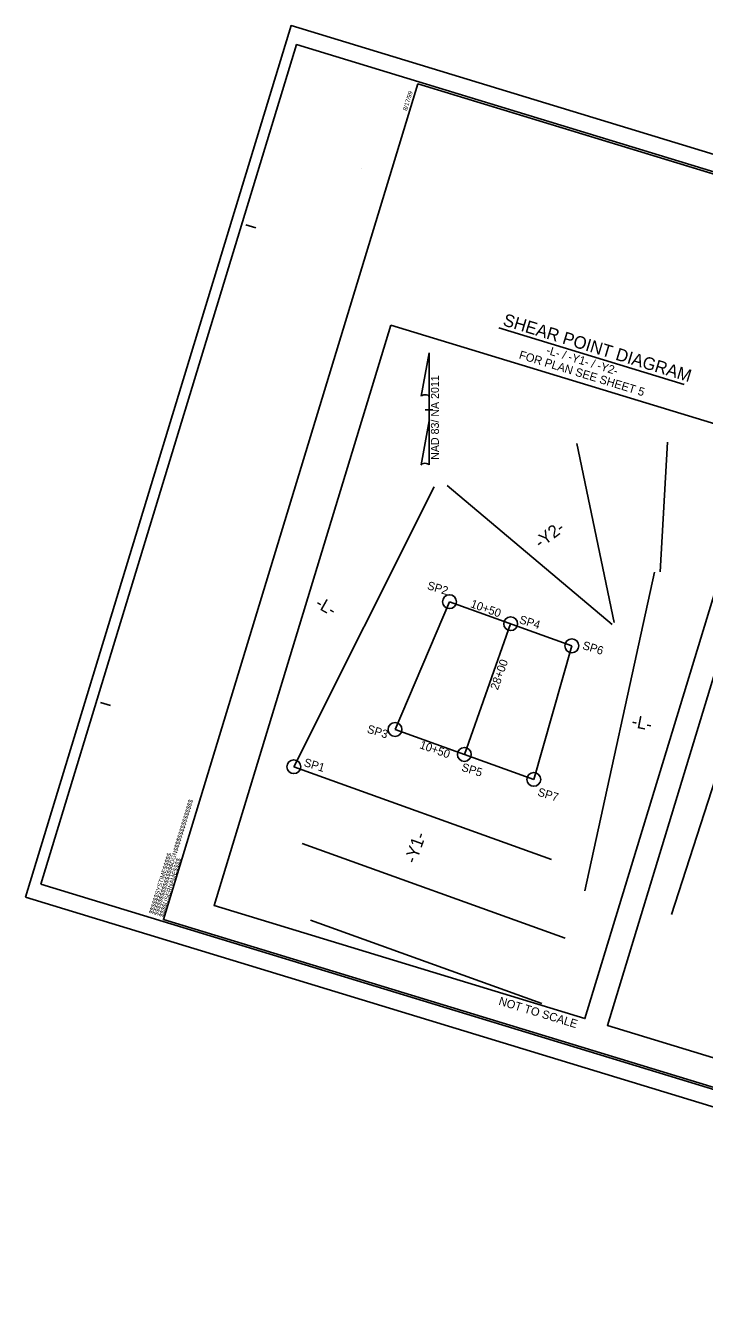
# Model space of a CAD drawing. Extents: x 1619199 to 1620423, y 897643 to 898566.
# Drawn here: x 1619199 to 1619689, y 897643 to 898566 of the extents above; entities that cross this region are included whole.
import ezdxf

# ---------------------------------------------------------------- set-up
doc = ezdxf.new("R2010")
doc.units = 0
for name, color, linetype in [('Default', 7, 'Continuous'), ('Prop North Arrow NAD83 for Plan Sheets CELL', 7, 'Continuous'), ('Sheet Plan CELL', 7, 'Continuous'), ('Sheet Plot Border Inside CELL', 7, 'Continuous'), ('Sheet Plot Border Outside CELL', 7, 'Continuous')]:
    doc.layers.add(name, color=color, linetype=linetype)

msp = doc.modelspace()

# ---------------------------------------------------------------- linework, layer by layer
at = {"layer": 'Default'}
for p, q in [((1619540.4, 898347.62), (1619674.25, 898306.83)), ((1619596.78, 898264.34), (1619623.54, 898135.11)), ((1619662.14, 898265.23), (1619656.92, 898171.77)), ((1619493.85, 898232.98), (1619392.46, 898031.21)), ((1619503.07, 898234.12), (1619622.08, 898133.89)), ((1619652.82, 898171.6), (1619602.45, 897941.66)), ((1619504.77, 898150.21), (1619465.48, 898058.08)), ((1619504.77, 898150.21), (1619593.11, 898118.44)), ((1619548.93, 898134.33), (1619515.52, 898040.08)), ((1619593.11, 898118.44), (1619565.59, 898022.07)), ((1619714.16, 898076.98), (1619664.97, 897924.73)), ((1619565.59, 898022.07), (1619465.48, 898058.08)), ((1619578.49, 897964.29), (1619392.46, 898031.21)), ((1619588.37, 897907.6), (1619398.52, 897975.89)), ((1619571.44, 897860.55), (1619404.59, 897920.57))]:
    msp.add_line(p, q, dxfattribs=at)
for points in [[(1619462.5, 898349.68), (1619730.07, 898268.15), (1619602.5, 897849.59), (1619334.95, 897931.12)], [(1620036.23, 898176.17), (1619908.29, 897756.39), (1619618.7, 897844.65), (1619746.28, 898263.24)], [(1620035.83, 898174.97), (1619908.21, 897756.39), (1619618.7, 897844.65), (1619746.31, 898263.23)]]:
    msp.add_lwpolyline(points, close=True, dxfattribs=at)
for centre in [(1619504.77, 898150.21), (1619548.93, 898134.33), (1619593.11, 898118.44), (1619465.48, 898058.08), (1619515.52, 898040.08), (1619392.46, 898031.21), (1619565.59, 898022.07)]:
    msp.add_circle(centre, 5, dxfattribs=at)
at = {"layer": 'Prop North Arrow NAD83 for Plan Sheets CELL'}
for p, q in [((1619484.47, 898298.42), (1619490.01, 898329.7)), ((1619490.04, 898329.7), (1619490.01, 898329.7)), ((1619490.04, 898329.7), (1619490.01, 898329.7)), ((1619490.04, 898329.7), (1619490.04, 898297.44)), ((1619490.04, 898280.7), (1619490.04, 898298.38)), ((1619490.04, 898297.44), (1619490.04, 898298.35)), ((1619487.34, 898288.53), (1619487.31, 898288.53)), ((1619489.74, 898288.53), (1619487.34, 898288.53)), ((1619487.38, 898288.53), (1619492.78, 898288.53)), ((1619490.04, 898280.7), (1619484.41, 898248.81)), ((1619490.08, 898248.94), (1619490.04, 898280.7))]:
    msp.add_line(p, q, dxfattribs=at)
for centre, start_param, end_param in [((1619487.27, 898298.08), 0.216388, 2.908219), ((1619487.27, 898248.69), 0.201328, 3.141593)]:
    msp.add_ellipse(centre, major_axis=(2.86, -0.02), ratio=0.461098, start_param=start_param, end_param=end_param, dxfattribs=at)
at = {"layer": 'Sheet Plan CELL'}
for p, q in [((1619441.3, 898462.92), (1619441.3, 898462.92)), ((1619357.91, 898421.91), (1619365.09, 898419.74)), ((1619252.97, 898077.56), (1619260.14, 898075.36))]:
    msp.add_line(p, q, dxfattribs=at)
for points in [[(1620342.99, 898261.25), (1619482.06, 898523.65), (1619298.39, 897921.02), (1620159.3, 897658.63)], [(1619298.39, 897921.02), (1619482.05, 898523.64), (1620228.16, 898296.26), (1620201.92, 898210.13), (1620316.72, 898175.13), (1620159.3, 897658.63)]]:
    msp.add_lwpolyline(points, close=True, dxfattribs=at)
at = {"layer": 'Sheet Plot Border Inside CELL'}
msp.add_lwpolyline([(1619209.86, 897946.43), (1620166.03, 897655.01), (1620350.58, 898260.5), (1619394.41, 898551.93)], close=True, dxfattribs=at)
at = {"layer": 'Sheet Plot Border Outside CELL'}
msp.add_lwpolyline([(1619198.9, 897937.22), (1620165.12, 897642.73), (1620356.66, 898271.19), (1619390.44, 898565.68)], close=True, dxfattribs=at)

# ---------------------------------------------------------------- texts
at = {"layer": 'Default'}
for s, height, rotation, p in [('SHEAR POINT DIAGRAM', 9, 343.04954, (1619542.77, 898349.63)), ('-L- / -Y1- / -Y2-', 6, 343.04954, (1619574.16, 898329.14)), ('FOR PLAN SEE SHEET 5', 6, 343.04954, (1619554.5, 898325.72)), ('-Y2-', 9, 36.80875, (1619570.38, 898188.23)), ('SP2', 6, 343.04954, (1619488.22, 898159.4)), ('-L-', 9, 330.50678, (1619407.2, 898146.74)), ('10+50', 6, 340.21645, (1619519.49, 898146.38)), ('SP4', 6, 343.04954, (1619554.66, 898134.79)), ('SP6', 6, 343.04954, (1619600.29, 898116.21)), ('28+00', 6, 70.48161, (1619539.67, 898086.1)), ('-L-', 9, 349.08421, (1619635.67, 898059.94)), ('SP3', 6, 343.04954, (1619444.85, 898055.91)), ('10+50', 6, 340.21645, (1619482.72, 898044.71)), ('SP1', 6, 343.04954, (1619399.21, 898031.79)), ('SP5', 6, 343.04954, (1619512.95, 898028.34)), ('SP7', 6, 343.04954, (1619567.9, 898010.48)), ('-Y1-', 9, 70.21645, (1619480.38, 897960.76)), ('NOT TO SCALE', 6, 343.04954, (1619539.84, 897859.72))]:
    msp.add_text(s, height=height, rotation=rotation, dxfattribs=at).set_placement(p)
at = {"layer": 'Prop North Arrow NAD83 for Plan Sheets CELL'}
msp.add_text('NAD 83/ NA 2011', height=5.7375, rotation=90, dxfattribs=at).set_placement((1619497.14, 898252.52))
at = {"layer": 'Sheet Plan CELL'}
for s, p in [('8/17/99', (1619474.05, 898504)), ('$$$$$$$$$$$$$$$$DGN$$$$$$$$$$$$$$$$', (1619294.42, 897923.71)), ('$$$$$$SYSTIME$$$$$', (1619290.93, 897924.76)), ('$$$$USERNAME$$$$', (1619298.18, 897922.57))]:
    msp.add_text(s, height=3.15, rotation=73.04955, dxfattribs=at).set_placement(p)

doc.saveas('drawing.dxf')
